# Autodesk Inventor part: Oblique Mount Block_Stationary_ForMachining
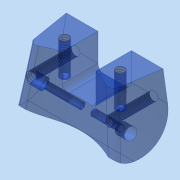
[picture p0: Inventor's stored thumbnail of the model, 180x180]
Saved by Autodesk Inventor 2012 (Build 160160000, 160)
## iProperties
Created: 2013-11
Part Number: Oblique Mount Block_Stationary_ForMachining
Material: Aluminum-6061
Document SubType Name: Modeling
Designer: Owner
Density: 2.71 g/cm^3
Mass: 81.9109 g
Surface Area: 96.2624 cm^2
Volume: 30.2254 cm^3
Author: Owner
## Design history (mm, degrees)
sketch "Sketch1"
  geometry: L1 (0, 0)-(66.675, 0); L2 (66.675, 0)-(66.675, -34.925); L3 (66.675, -34.925)-(0, -34.925); L4 (0, -34.925)-(0, 0)
  constraints: 8 end point, 2 parallel, 1 horizontal, 1 perpendicular
  dimensions: "d0" = 66.675 distance of L1.start L1.end; "d1" = 34.925 distance of L3.end L1.start
extrude "Extrusion1" new body sketch "Sketch1" distance "d2" = 31.75; taper "d3" = 0 deg
sketch "Sketch2"
  geometry: L1 (66.675, 0)-(66.675, 31.75) reference; L2 (49.213, 19.05)-(17.462, 19.05); L3 (66.675, 31.75)-(0, 31.75) reference; L4 (33.338, 19.05)-(33.338, 31.75)
  constraints: 4 end point, 2 midpoint, 1 perpendicular, 1 vertical
  dimensions: "d4" = 31.75 distance of L2.start L2.end; "d53" = 12.7 distance of L4.start L4.end
hole "Hole1" sketch "Sketch2" at (17.462, 19.05), (49.213, 19.05) diameter "d6" = 4.9784; stored, may be unused: countersink angle "d10" = 82 deg, drill point angle "d12" = 118 deg; dims "d7" = 12.7, "d8" = 9.525, "d9" = 6.35, "d11" = 19.05
sketch "Sketch3"
  geometry: L1 (0, 0)-(66.675, 0) reference; L2 (66.675, 0)-(66.675, -34.925) reference; L3 (11.113, -15.875)-(55.562, -15.875); L4 (33.338, -15.875)-(33.338, 0); 2 further points
  constraints: 4 end point, 2 coincident, 2 midpoint, 1 perpendicular, 1 vertical
  dimensions: "d13" = 15.875 distance between parallel lines of L1 L3; "d14" = 44.45 distance of L3.start L3.end
hole "Hole2" sketch "Sketch3" at (11.113, -15.875), (55.562, -15.875) diameter "d15" = 4.9784; stored, may be unused: countersink angle "d19" = 82 deg, drill point angle "d21" = 118 deg; dims "d16" = 12.7, "d17" = 9.525, "d18" = 6.35, "d20" = 25.4
workplane "Work Plane1"
sketch "Sketch12"
  geometry: L1 (-66.675, -24.696)-(-55.671, 22.451); L2 (0, 22.451)-(-66.675, 22.451) reference; L3 (-55.671, 22.451)-(-66.675, 22.451); L4 (-66.675, -24.696)-(-66.675, 22.451); L5 (0, -24.696)-(0, 22.451); L6 (-11.004, 22.451)-(0, 22.451); L7 (-11.004, 22.451)-(0, -24.696)
  constraints: 12 end point, 2 perpendicular, 1 collinear, 1 parallel, 1 point on line
  dimensions: "d55" = 13.138 deg angle of L4 L1; "d56" = 13.138 deg angle of L5 L7 (= d55)
extrude "Extrusion9" cut sketch "Sketch12" stored distance "d57" = 25.4; taper "d58" = 0 deg
sketch "Sketch14"
  geometry: L1 (-34.925, -31.75)-(0, -31.75) reference; L2 (0, 0)-(-34.925, 0) reference; L3 (0, -31.75)-(0, 0) reference; L4 (-34.925, 0)-(-34.925, -31.75) reference; L5 (-15.875, -31.75)-(-34.925, -31.75); L6 (-34.925, -31.75)-(-34.925, 0); L7 (-34.925, 0)-(-22.225, 0); A1 r 19.05 centre (-15.875, -12.7) between (-34.925, -12.7) and (-15.875, -31.75); A2 r 12.7 centre (-22.225, -12.7) between (-22.225, 0) and (-34.925, -12.7)
  constraints: 6 end point, 4 point on circle, 4 tangent, 3 point on line, 2 centre point, 1 collinear, 1 perpendicular
  dimensions: "d90" = 19.05 distance from line of L1 A1.start
extrude "Extrusion10" cut sketch "Sketch14" stored distance "d60" = 25.4; taper "d61" = 0 deg
hole "Hole3" diameter "d64" = 3.683; stored, may be unused: countersink angle "d68" = 82 deg, drill point angle "d70" = 118 deg; dims "d65" = 19.05, "d66" = 9.525, "d67" = 6.35, "d69" = 25.4, "d91" = 25.4, "d92" = 25.4
sketch "Sketch15"
  geometry: C1 r 3.175 at (18.71, -22.518); 5 further points; 1 other entity
  constraints: 1 centre point, 2 other
  dimensions: "d73" = 6.35 diameter of C1
extrude "Extrusion11" cut sketch "Sketch15" distance "d74" = 6.35; taper "d75" = 0 deg
hole "Hole4" diameter "d78" = 3.683; stored, may be unused: countersink angle "d82" = 82 deg, drill point angle "d84" = 118 deg; dims "d79" = 19.05, "d80" = 9.525, "d81" = 6.35, "d83" = 25.4, "d93" = 25.4, "d94" = 25.4
sketch "Sketch16"
  geometry: C1 r 3.175 at (13.469, -22.518); 5 further points; 1 other entity
  constraints: 1 centre point, 2 other
  dimensions: "d85" = 6.35 diameter of C1
extrude "Extrusion12" cut sketch "Sketch16" distance "d86" = 6.35; taper "d87" = 0 deg
sketch "Sketch17"
  geometry: L1 (0, 0)-(44.666, 0) reference; L2 (49.907, 31.75)-(-5.24, 31.75) reference; L3 (22.333, 0)-(22.333, -25.4); C1 r 38.1 at (22.333, -25.4); 1 further point
  constraints: 2 end point, 1 centre point, 1 coincident, 1 midpoint, 1 perpendicular
  dimensions: "d95" = 57.15 distance from line of L3.end L2; "d96" = 76.2 diameter of C1
extrude "Extrusion13" cut sketch "Sketch17" stored distance "d97" = 0; taper "d98" = 0 deg
sketch "Sketch18"
  geometry: L1 (-60.911, 0)-(-5.764, 0) reference; L2 (-23.813, 0)-(-42.863, 0); L3 (-42.863, 0)-(-42.863, -15.875); L4 (-39.688, -19.05)-(-26.988, -19.05); L5 (-23.813, -15.875)-(-23.813, 0); L6 (-33.338, -19.05)-(-33.338, 0); A1 r 3.175 centre (-39.688, -15.875) between (-42.863, -15.875) and (-39.688, -19.05); A2 r 3.175 centre (-26.988, -15.875) between (-26.988, -19.05) and (-23.813, -15.875); 1 further point
  constraints: 10 end point, 4 point on circle, 4 tangent, 2 centre point, 2 midpoint, 2 parallel, 1 equal radius, 1 horizontal, 1 perpendicular, 1 point on line, 1 vertical
  dimensions: "d99" = 19.05 distance of L6.start L6.end; "d100" = 19.05 distance between parallel lines of L5 L3; "d101" = 3.175 radius of A1
extrude "Extrusion14" cut sketch "Sketch18" stored distance "d102" = 12.7; taper "d103" = 0 deg
fillet "Fillet1" dims "d104" = 3.175
body "Solid1"
other parameters: "d54" = 45 deg
